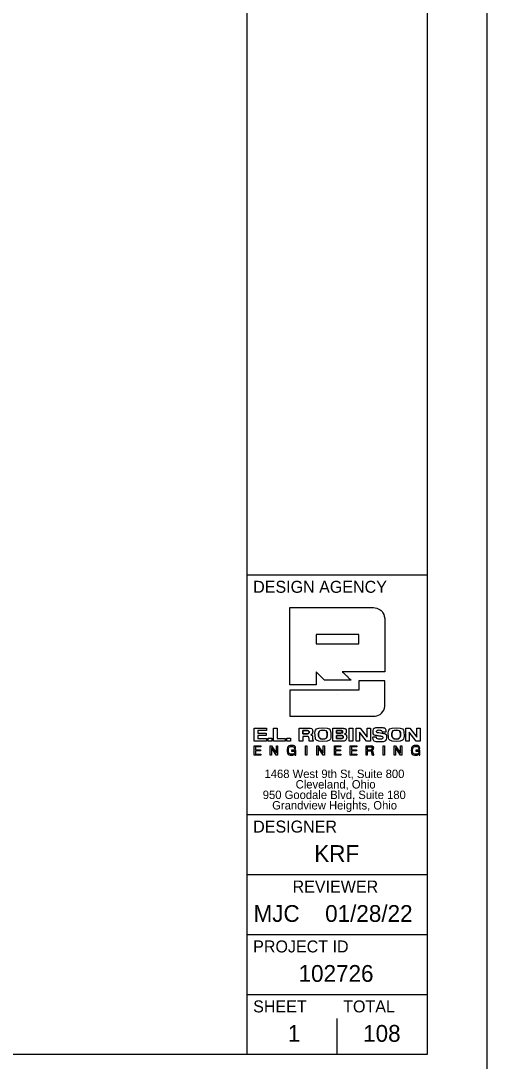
# Model space of a CAD drawing. Extents: x 0 to 34, y -4 to 22.
# Drawn here: x 30.11 to 34, y 0.44 to 9.12 of the extents above; entities that cross this region are included whole.
import ezdxf

# ---------------------------------------------------------------- set-up
doc = ezdxf.new("R2010")
doc.units = 0
for name, color, linetype in [('SH_Border', 7, 'Continuous'), ('SH_Cut_Line', 7, 'Continuous'), ('SH_Data', 7, 'Continuous')]:
    doc.layers.add(name, color=color, linetype=linetype)

msp = doc.modelspace()

# ---------------------------------------------------------------- linework, layer by layer
at = {"layer": 'SH_Border'}
for p, q in [((32, 0.5), (32, 21.5)), ((32, 4.5), (33.5, 4.5)), ((32, 2.5), (33.5, 2.5)), ((32, 2), (33.5, 2)), ((32, 1.5), (33.5, 1.5)), ((32, 1), (33.5, 1))]:
    msp.add_line(p, q, dxfattribs=at)
msp.add_lwpolyline([(1.5, 21.5), (33.5, 21.5), (33.5, 0.5), (1.5, 0.5)], close=True, dxfattribs=at)
at = {"layer": 'SH_Cut_Line'}
msp.add_lwpolyline([(0, 0), (34, 0), (34, 22), (0, 22)], close=True, dxfattribs=at)
at = {"layer": 'SH_Data'}
for p, q in [((32.9293, 4.0026), (32.574, 4.0026)), ((32.574, 4.0026), (32.574, 3.9255)), ((32.9293, 3.9255), (32.9293, 4.0026)), ((32.574, 3.9255), (32.9293, 3.9255)), ((32.75, 3.5), (32.75, 3.5)), ((32.4626, 3.2007), (32.4626, 3.1733)), ((32.7434, 3.2016), (32.7434, 3.1781)), ((32.7434, 3.1593), (32.7434, 3.1334)), ((33.0012, 3.0659), (33.0012, 3.0385)), ((33.0012, 3.0385), (33.0229, 3.0385)), ((32.75, 0.5), (32.75, 0.8)), ((32.375, 0.675), (32.375, 0.675))]:
    msp.add_line(p, q, dxfattribs=at)
for points in [[(32.0596, 3.2214), (32.1612, 3.2214), (32.1612, 3.2007), (32.0892, 3.2007), (32.0892, 3.1781), (32.1575, 3.1781), (32.1575, 3.1584), (32.0892, 3.1584), (32.0892, 3.1334), (32.1618, 3.1334), (32.1618, 3.1127), (32.0596, 3.1127), (32.0596, 3.2214)], [(32.2198, 3.2214), (32.2493, 3.2214), (32.2493, 3.1343), (32.3155, 3.1343), (32.3155, 3.1127), (32.2198, 3.1127), (32.2198, 3.2214)], [(32.8512, 3.2214), (32.8807, 3.2214), (32.8807, 3.1127), (32.8512, 3.1127), (32.8512, 3.2214)], [(32.9989, 3.2214), (33.0275, 3.2214), (33.0275, 3.1127), (32.9954, 3.1127), (32.9361, 3.1885), (32.9358, 3.1885), (32.9358, 3.1127), (32.9072, 3.1127), (32.9072, 3.2214), (32.9415, 3.2214), (32.9986, 3.1456), (32.9989, 3.1456), (32.9989, 3.2214)], [(33.413, 3.2214), (33.4416, 3.2214), (33.4416, 3.1127), (33.4095, 3.1127), (33.3503, 3.1885), (33.35, 3.1885), (33.35, 3.1127), (33.3213, 3.1127), (33.3213, 3.2214), (33.3556, 3.2214), (33.4127, 3.1456), (33.413, 3.1456), (33.413, 3.2214)], [(32.1751, 3.1386), (32.2047, 3.1386), (32.2047, 3.1127), (32.1751, 3.1127), (32.1751, 3.1386)], [(32.3311, 3.1386), (32.3606, 3.1386), (32.3606, 3.1127), (32.3311, 3.1127), (32.3311, 3.1386)], [(32.0594, 3.0747), (32.1135, 3.0747), (32.1135, 3.0659), (32.0698, 3.0659), (32.0698, 3.041), (32.1105, 3.041), (32.1105, 3.0322), (32.0698, 3.0322), (32.0698, 3.0051), (32.1138, 3.0051), (32.1138, 2.9963), (32.0594, 2.9963), (32.0594, 3.0747)], [(32.1915, 3.0747), (32.2026, 3.0747), (32.2439, 3.0111), (32.2441, 3.0111), (32.2441, 3.0747), (32.254, 3.0747), (32.254, 2.9963), (32.2426, 2.9963), (32.2016, 3.0592), (32.2014, 3.0592), (32.2014, 2.9963), (32.1915, 2.9963), (32.1915, 3.0747)], [(32.4873, 3.0747), (32.4977, 3.0747), (32.4977, 2.9963), (32.4873, 2.9963), (32.4873, 3.0747)], [(32.5808, 3.0747), (32.5919, 3.0747), (32.6332, 3.0111), (32.6334, 3.0111), (32.6334, 3.0747), (32.6433, 3.0747), (32.6433, 2.9963), (32.6319, 2.9963), (32.5909, 3.0592), (32.5907, 3.0592), (32.5907, 2.9963), (32.5808, 2.9963), (32.5808, 3.0747)], [(32.7264, 3.0747), (32.7805, 3.0747), (32.7805, 3.0659), (32.7368, 3.0659), (32.7368, 3.041), (32.7776, 3.041), (32.7776, 3.0322), (32.7368, 3.0322), (32.7368, 3.0051), (32.7809, 3.0051), (32.7809, 2.9963), (32.7264, 2.9963), (32.7264, 3.0747)], [(32.8586, 3.0747), (32.9127, 3.0747), (32.9127, 3.0659), (32.869, 3.0659), (32.869, 3.041), (32.9097, 3.041), (32.9097, 3.0322), (32.869, 3.0322), (32.869, 3.0051), (32.913, 3.0051), (32.913, 2.9963), (32.8586, 2.9963), (32.8586, 3.0747)], [(33.1327, 3.0747), (33.1431, 3.0747), (33.1431, 2.9963), (33.1327, 2.9963), (33.1327, 3.0747)], [(33.2263, 3.0747), (33.2374, 3.0747), (33.2786, 3.0111), (33.2789, 3.0111), (33.2789, 3.0747), (33.2887, 3.0747), (33.2887, 2.9963), (33.2773, 2.9963), (33.2364, 3.0592), (33.2361, 3.0592), (33.2361, 2.9963), (33.2263, 2.9963), (33.2263, 3.0747)]]:
    msp.add_lwpolyline(points, dxfattribs=at)
for points, degree in [([(32.3563, 3.5827), (32.3563, 3.5858), (32.3563, 4.2242), (32.3563, 4.2273)], 2), ([(32.3563, 4.2273), (32.3596, 4.2273), (33.0304, 4.2273), (33.0337, 4.2273), (33.0963, 4.2273), (33.147, 4.1766), (33.147, 4.1139)], 3), ([(33.147, 4.1139), (33.147, 4.1119), (33.147, 3.6938), (33.147, 3.6917)], 2), ([(32.6452, 3.6205), (32.6448, 3.6209), (32.5744, 3.6914), (32.574, 3.6917)], 2), ([(32.574, 3.6917), (32.574, 3.6912), (32.574, 3.5832), (32.574, 3.5827)], 2), ([(33.147, 3.6917), (33.1453, 3.6917), (32.7946, 3.6917), (32.7929, 3.6917)], 2), ([(32.7929, 3.6917), (32.7933, 3.6914), (32.8658, 3.6209), (32.8662, 3.6205)], 2), ([(32.574, 3.5827), (32.573, 3.5827), (32.3574, 3.5827), (32.3563, 3.5827)], 2), ([(32.9293, 3.6146), (32.9293, 3.6146), (33.147, 3.6146), (33.147, 3.6146), (33.147, 3.6146), (33.147, 3.4329), (33.147, 3.4329), (33.147, 3.3703), (33.0963, 3.3196), (33.0337, 3.3196), (33.0337, 3.3196), (32.3563, 3.3196), (32.3563, 3.3196), (32.3563, 3.3196), (32.3563, 3.5374), (32.3563, 3.5374), (32.3563, 3.5374), (32.9293, 3.5374), (32.9293, 3.5374), (32.9293, 3.5374), (32.9293, 3.6146), (32.9293, 3.6146)], 3), ([(32.8662, 3.6205), (32.8651, 3.6205), (32.6463, 3.6205), (32.6452, 3.6205)], 2), ([(32.4331, 3.1127), (32.4331, 3.1132), (32.4331, 3.2209), (32.4331, 3.2214)], 2), ([(32.4331, 3.2214), (32.4335, 3.2214), (32.5117, 3.2214), (32.5121, 3.2214), (32.5423, 3.2214), (32.5454, 3.2027), (32.5463, 3.1918)], 3), ([(32.6312, 3.1096), (32.5727, 3.1096), (32.5671, 3.1449), (32.5653, 3.1672), (32.5636, 3.1897), (32.5727, 3.2244), (32.6312, 3.2244)], 3), ([(32.6312, 3.2244), (32.6896, 3.2244), (32.6953, 3.1892), (32.697, 3.1669), (32.6988, 3.1443), (32.6896, 3.1096), (32.6312, 3.1096)], 3), ([(32.7138, 3.2214), (32.7142, 3.2214), (32.7951, 3.2214), (32.7955, 3.2214)], 2), ([(32.7138, 3.1127), (32.7138, 3.1132), (32.7138, 3.2209), (32.7138, 3.2214)], 2), ([(32.7955, 3.2214), (32.8104, 3.2178), (32.8261, 3.2141), (32.8261, 3.194)], 2), ([(33.1262, 3.1899), (33.1243, 3.204), (33.1108, 3.2056), (33.0989, 3.2056), (33.0867, 3.2056), (33.0788, 3.2001), (33.0788, 3.1928), (33.0788, 3.187), (33.0837, 3.1838), (33.0913, 3.1826), (33.0913, 3.1826), (33.1283, 3.1766), (33.1283, 3.1766), (33.1481, 3.1734), (33.1632, 3.166), (33.1632, 3.1462), (33.1632, 3.1259), (33.1494, 3.1096), (33.1067, 3.1096), (33.0802, 3.1096), (33.0458, 3.113), (33.0454, 3.1469), (33.0454, 3.1469), (33.0786, 3.1469), (33.0786, 3.1469), (33.0789, 3.132), (33.0939, 3.1294), (33.1067, 3.1294), (33.1205, 3.1294), (33.13, 3.1335), (33.13, 3.143), (33.13, 3.1513), (33.1233, 3.1536), (33.1115, 3.1555), (33.1115, 3.1555), (33.0846, 3.1596), (33.0846, 3.1596), (33.0657, 3.1625), (33.0474, 3.1681), (33.0474, 3.1903), (33.0474, 3.2145), (33.0672, 3.2244), (33.1013, 3.2244), (33.1237, 3.2244), (33.1569, 3.2206), (33.1589, 3.1899), (33.1589, 3.1899), (33.1262, 3.1899), (33.1262, 3.1899)], 3), ([(33.2417, 3.1096), (33.1832, 3.1096), (33.1776, 3.1449), (33.1759, 3.1672), (33.1741, 3.1897), (33.1832, 3.2244), (33.2417, 3.2244)], 3), ([(33.2417, 3.2244), (33.3002, 3.2244), (33.3058, 3.1892), (33.3075, 3.1669), (33.3093, 3.1443), (33.3002, 3.1096), (33.2417, 3.1096)], 3), ([(32.4993, 3.1526), (32.4991, 3.1526), (32.4628, 3.1526), (32.4626, 3.1526)], 2), ([(32.4626, 3.1733), (32.4626, 3.1733), (32.5018, 3.1733), (32.5018, 3.1733), (32.5083, 3.1733), (32.5159, 3.1769), (32.5159, 3.1871), (32.5159, 3.1979), (32.5074, 3.2007), (32.5002, 3.2007), (32.5002, 3.2007), (32.4626, 3.2007), (32.4626, 3.2007), (32.4626, 3.2007), (32.4626, 3.1733), (32.4626, 3.1733)], 3), ([(32.4626, 3.1733), (32.4757, 3.1733), (32.4887, 3.1733), (32.5083, 3.1733), (32.5159, 3.1769), (32.5159, 3.1979), (32.5074, 3.2007), (32.4877, 3.2007), (32.4752, 3.2007), (32.4626, 3.2007)], 3), ([(32.4626, 3.1526), (32.4626, 3.1524), (32.4626, 3.1129), (32.4626, 3.1127)], 2), ([(32.5179, 3.1127), (32.5162, 3.118), (32.5159, 3.1222), (32.5155, 3.1335), (32.515, 3.1488), (32.5079, 3.1505), (32.4993, 3.1526)], 3), ([(32.5463, 3.1918), (32.5438, 3.1793), (32.542, 3.1701), (32.5296, 3.1657)], 2), ([(32.5296, 3.1657), (32.5296, 3.1657), (32.5296, 3.1654), (32.5296, 3.1654)], 2), ([(32.5296, 3.1654), (32.5426, 3.1634), (32.5438, 3.1469), (32.5443, 3.1363)], 2), ([(32.5443, 3.1363), (32.5445, 3.1309), (32.5482, 3.1191), (32.5502, 3.1127)], 2), ([(32.6312, 3.1303), (32.658, 3.1303), (32.6674, 3.1501), (32.6674, 3.167), (32.6674, 3.1839), (32.658, 3.2037), (32.6312, 3.2037), (32.6044, 3.2037), (32.5949, 3.1839), (32.5949, 3.167), (32.5949, 3.1501), (32.6044, 3.1303), (32.6312, 3.1303)], 3), ([(32.6312, 3.2037), (32.6044, 3.2037), (32.5949, 3.1839), (32.5949, 3.167), (32.5949, 3.1501), (32.6044, 3.1303), (32.6312, 3.1303)], 3), ([(32.6312, 3.1303), (32.658, 3.1303), (32.6674, 3.1501), (32.6674, 3.167), (32.6674, 3.1839), (32.658, 3.2037), (32.6312, 3.2037)], 3), ([(32.8292, 3.1454), (32.8271, 3.1317), (32.8242, 3.1127), (32.7913, 3.1127), (32.791, 3.1127), (32.7142, 3.1127), (32.7138, 3.1127)], 3), ([(32.7434, 3.1781), (32.7434, 3.1781), (32.7845, 3.1781), (32.7845, 3.1781), (32.7913, 3.1781), (32.7956, 3.1818), (32.7956, 3.1899), (32.7956, 3.1967), (32.7926, 3.2016), (32.7804, 3.2016), (32.7804, 3.2016), (32.7434, 3.2016), (32.7434, 3.2016), (32.7434, 3.2016), (32.7434, 3.1781), (32.7434, 3.1781)], 3), ([(32.7434, 3.1781), (32.7571, 3.1781), (32.7708, 3.1781), (32.7909, 3.1811), (32.7915, 3.183), (32.7923, 3.1969), (32.7926, 3.2016), (32.768, 3.2016), (32.7557, 3.2016), (32.7434, 3.2016)], 3), ([(32.7434, 3.1334), (32.7434, 3.1334), (32.7869, 3.1334), (32.7869, 3.1334), (32.7961, 3.1334), (32.7996, 3.1393), (32.7996, 3.1462), (32.7996, 3.1547), (32.7942, 3.1593), (32.7839, 3.1593), (32.7839, 3.1593), (32.7434, 3.1593), (32.7434, 3.1593), (32.7434, 3.1593), (32.7434, 3.1334), (32.7434, 3.1334)], 3), ([(32.7434, 3.1334), (32.7579, 3.1334), (32.7724, 3.1334), (32.7961, 3.1334), (32.7996, 3.1393), (32.7996, 3.1547), (32.7942, 3.1593), (32.7704, 3.1593), (32.7569, 3.1593), (32.7434, 3.1593)], 3), ([(32.8261, 3.194), (32.8242, 3.186), (32.8218, 3.1754), (32.8116, 3.1722)], 2), ([(32.8116, 3.1722), (32.8116, 3.1722), (32.8116, 3.1719), (32.8116, 3.1719)], 2), ([(32.8116, 3.1719), (32.8242, 3.1698), (32.827, 3.1563), (32.8292, 3.1454)], 2), ([(33.2417, 3.1303), (33.2685, 3.1303), (33.278, 3.1501), (33.278, 3.167), (33.278, 3.1839), (33.2685, 3.2037), (33.2417, 3.2037), (33.2149, 3.2037), (33.2055, 3.1839), (33.2055, 3.167), (33.2055, 3.1501), (33.2149, 3.1303), (33.2417, 3.1303)], 3), ([(33.2417, 3.2037), (33.2149, 3.2037), (33.2055, 3.1839), (33.2055, 3.167), (33.2055, 3.1501), (33.2149, 3.1303), (33.2417, 3.1303)], 3), ([(33.2417, 3.1303), (33.2685, 3.1303), (33.278, 3.1501), (33.278, 3.167), (33.278, 3.1839), (33.2685, 3.2037), (33.2417, 3.2037)], 3), ([(32.3956, 3.006), (32.3896, 2.9978), (32.3797, 2.9944), (32.3705, 2.9944), (32.3471, 2.9944), (32.3332, 3.0135), (32.3332, 3.0339), (32.3332, 3.0568), (32.3457, 3.0765), (32.3705, 3.0765), (32.3876, 3.0765), (32.4012, 3.0689), (32.4042, 3.0505), (32.4042, 3.0505), (32.3938, 3.0505), (32.3938, 3.0505), (32.3917, 3.0624), (32.3821, 3.0678), (32.3705, 3.0678), (32.3515, 3.0678), (32.3436, 3.0513), (32.3436, 3.0345), (32.3436, 3.0181), (32.353, 3.0032), (32.3705, 3.0032), (32.3866, 3.0032), (32.3963, 3.0145), (32.3956, 3.0288), (32.3956, 3.0288), (32.3706, 3.0288), (32.3706, 3.0288), (32.3706, 3.0288), (32.3706, 3.0376), (32.3706, 3.0376), (32.3706, 3.0376), (32.405, 3.0376), (32.405, 3.0376), (32.405, 3.0376), (32.405, 2.9963), (32.405, 2.9963), (32.405, 2.9963), (32.3984, 2.9963), (32.3984, 2.9963), (32.3984, 2.9963), (32.3956, 3.006), (32.3956, 3.006)], 3), ([(32.4626, 3.1127), (32.4625, 3.1127), (32.4332, 3.1127), (32.4331, 3.1127)], 2), ([(32.5502, 3.1127), (32.55, 3.1127), (32.518, 3.1127), (32.5179, 3.1127)], 2), ([(32.9907, 2.9963), (32.9907, 2.9967), (32.9907, 3.0743), (32.9907, 3.0747)], 2), ([(32.9907, 3.0747), (32.9909, 3.0747), (33.0274, 3.0747), (33.0276, 3.0747), (33.0423, 3.0747), (33.0515, 3.0667), (33.0515, 3.0541)], 3), ([(33.0229, 3.0385), (33.0327, 3.0385), (33.041, 3.0411), (33.041, 3.0525), (33.041, 3.0602), (33.0369, 3.0659), (33.0271, 3.0659), (33.0271, 3.0659), (33.0012, 3.0659), (33.0012, 3.0659), (33.0012, 3.0659), (33.0012, 3.0385), (33.0012, 3.0385), (33.0012, 3.0385), (33.0229, 3.0385), (33.0229, 3.0385)], 3), ([(33.0229, 3.0385), (33.0327, 3.0385), (33.041, 3.0411), (33.041, 3.0602), (33.0369, 3.0659), (33.0184, 3.0659), (33.0098, 3.0659), (33.0012, 3.0659)], 3), ([(33.0515, 3.0541), (33.0493, 3.0452), (33.0473, 3.0369), (33.0378, 3.0343)], 2), ([(33.4304, 3.006), (33.4244, 2.9978), (33.4145, 2.9944), (33.4052, 2.9944), (33.3819, 2.9944), (33.3679, 3.0135), (33.3679, 3.0339), (33.3679, 3.0568), (33.3804, 3.0765), (33.4052, 3.0765), (33.4224, 3.0765), (33.436, 3.0689), (33.439, 3.0505), (33.439, 3.0505), (33.4285, 3.0505), (33.4285, 3.0505), (33.4264, 3.0624), (33.4169, 3.0678), (33.4052, 3.0678), (33.3863, 3.0678), (33.3783, 3.0513), (33.3783, 3.0345), (33.3783, 3.0181), (33.3878, 3.0032), (33.4052, 3.0032), (33.4214, 3.0032), (33.4311, 3.0145), (33.4304, 3.0288), (33.4304, 3.0288), (33.4054, 3.0288), (33.4054, 3.0288), (33.4054, 3.0288), (33.4054, 3.0376), (33.4054, 3.0376), (33.4054, 3.0376), (33.4397, 3.0376), (33.4397, 3.0376), (33.4397, 3.0376), (33.4397, 2.9963), (33.4397, 2.9963), (33.4397, 2.9963), (33.4331, 2.9963), (33.4331, 2.9963), (33.4331, 2.9963), (33.4304, 3.006), (33.4304, 3.006)], 3), ([(33.0012, 2.9963), (33.0011, 2.9963), (32.9908, 2.9963), (32.9907, 2.9963)], 2), ([(33.0012, 3.0298), (33.0012, 3.0296), (33.0012, 2.9964), (33.0012, 2.9963)], 2), ([(33.0398, 3.0156), (33.0381, 3.0232), (33.0367, 3.0298), (33.0266, 3.0298), (33.0265, 3.0298), (33.0013, 3.0298), (33.0012, 3.0298)], 3), ([(33.0378, 3.0343), (33.0378, 3.0343), (33.0378, 3.034), (33.0378, 3.034)], 2), ([(33.0378, 3.034), (33.0444, 3.029), (33.0465, 3.0245), (33.0483, 3.0176)], 2), ([(33.0426, 2.9963), (33.0422, 2.9997), (33.0409, 3.0079), (33.0398, 3.0156)], 2), ([(33.0542, 2.9963), (33.0541, 2.9963), (33.0426, 2.9963), (33.0426, 2.9963)], 2), ([(33.0483, 3.0176), (33.049, 3.0101), (33.0519, 3.0024), (33.0542, 2.9963)], 2)]:
    msp.add_open_spline(points, degree=degree, dxfattribs=at)

# ---------------------------------------------------------------- texts
for s, height, p in [('DESIGN AGENCY', 0.1, (32.05, 4.35)), ('1468 West 9th St, Suite 800', 0.07, (32.1445, 2.805)), ('Cleveland, Ohio', 0.07, (32.404, 2.7175)), ('950 Goodale Blvd, Suite 180', 0.07, (32.13, 2.63)), ('Grandview Heights, Ohio', 0.07, (32.2084, 2.5425)), ('DESIGNER', 0.1, (32.05, 2.35)), ('KRF', 0.14, (32.5588, 2.105)), ('REVIEWER', 0.1, (32.3783, 1.85)), ('MJC', 0.14, (32.0529, 1.605)), ('01/28/22', 0.14, (32.6497, 1.605)), ('PROJECT ID', 0.1, (32.05, 1.35)), ('102726', 0.14, (32.4282, 1.105)), ('SHEET', 0.1, (32.05, 0.85)), ('TOTAL', 0.1, (32.8, 0.85)), ('1', 0.14, (32.3386, 0.605)), ('108', 0.14, (32.9662, 0.605))]:
    msp.add_text(s, height=height, dxfattribs=at).set_placement(p)

doc.saveas('drawing.dxf')
